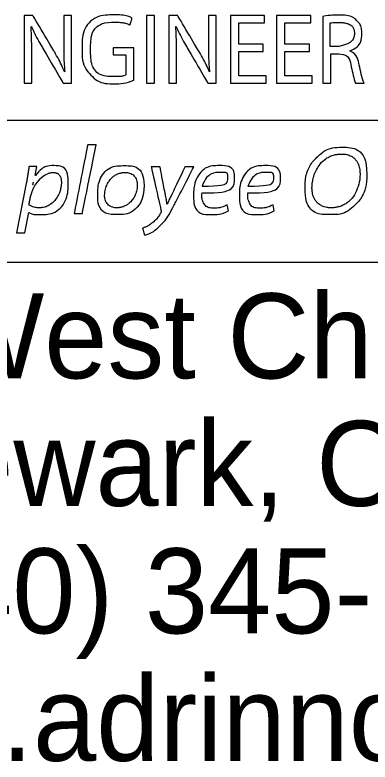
# Model space of a CAD drawing. Extents: x 0 to 34, y 0 to 22.
# Drawn here: x 32.435 to 32.774, y 3.227 to 3.941 of the extents above; entities that cross this region are included whole.
import ezdxf

# ---------------------------------------------------------------- set-up
doc = ezdxf.new("R2010")
doc.units = 0
doc.layers.add('SH_Data', color=7, linetype='Continuous')

msp = doc.modelspace()

# ---------------------------------------------------------------- linework, layer by layer
at = {"layer": 'SH_Data'}
for p, q in [((32.7567, 3.9307), (32.75677, 3.93063)), ((32.73689, 3.91095), (32.73609, 3.91095)), ((32.74792, 3.91193), (32.74453, 3.91095)), ((32.75255, 3.9136), (32.74792, 3.91193)), ((32.75492, 3.90673), (32.75492, 3.90702)), ((32.76039, 3.876), (32.76847, 3.876)), ((32.05557, 3.8407), (33.44039, 3.8407)), ((32.72917, 3.80154), (32.72917, 3.80154)), ((32.63877, 3.75393), (32.63761, 3.75966)), ((32.68262, 3.75393), (32.68145, 3.75966)), ((32.04831, 3.70477), (33.43313, 3.70477))]:
    msp.add_line(p, q, dxfattribs=at)
for points in [[(32.72909, 3.93966), (32.72909, 3.876), (32.73689, 3.876), (32.73689, 3.90395), (32.74425, 3.90395)], [(32.74453, 3.91095), (32.74439, 3.91095), (32.74425, 3.91095)], [(32.45431, 3.78768), (32.45412, 3.78768), (32.45547, 3.79619), (32.44811, 3.79619)], [(32.4455, 3.7802), (32.43611, 3.73303), (32.44405, 3.73303), (32.44782, 3.75236), (32.44802, 3.75236)], [(32.45188, 3.77893), (32.45189, 3.77898), (32.4519, 3.77904)], [(32.45116, 3.75804), (32.44806, 3.75976), (32.44806, 3.75976)], [(32.44806, 3.75976), (32.44806, 3.75976)]]:
    msp.add_lwpolyline(points, dxfattribs=at)
msp.add_arc((32.4781, 3.76327), 0.02878, 114.69426, 168.74282, dxfattribs=at)
for points, degree in [([(32.44333, 3.876), (32.44333, 3.876), (32.44333, 3.94052), (32.44333, 3.94052), (32.44333, 3.94052), (32.45185, 3.94052), (32.45185, 3.94052), (32.45185, 3.94052), (32.47123, 3.90788), (32.47123, 3.90788), (32.47572, 3.90031), (32.47922, 3.89352), (32.48209, 3.88691), (32.48209, 3.88691), (32.48227, 3.88701), (32.48227, 3.88701), (32.48155, 3.89562), (32.48137, 3.90347), (32.48137, 3.91352), (32.48137, 3.91352), (32.48137, 3.94052), (32.48137, 3.94052), (32.48137, 3.94052), (32.48873, 3.94052), (32.48873, 3.94052), (32.48873, 3.94052), (32.48873, 3.876), (32.48873, 3.876), (32.48873, 3.876), (32.48083, 3.876), (32.48083, 3.876), (32.48083, 3.876), (32.46163, 3.90874), (32.46163, 3.90874), (32.45742, 3.91592), (32.45338, 3.92329), (32.45033, 3.93027), (32.45033, 3.93027), (32.45006, 3.93018), (32.45006, 3.93018), (32.45051, 3.92204), (32.45069, 3.91429), (32.45069, 3.90357), (32.45069, 3.90357), (32.45069, 3.876), (32.45069, 3.876), (32.45069, 3.876), (32.44333, 3.876), (32.44333, 3.876)], 3), ([(32.54839, 3.87887), (32.54489, 3.87753), (32.53798, 3.87533), (32.52982, 3.87533), (32.52067, 3.87533), (32.51313, 3.87782), (32.50721, 3.88385), (32.50201, 3.88921), (32.49878, 3.89783), (32.49878, 3.90788), (32.49887, 3.92712), (32.51125, 3.94119), (32.53152, 3.94119), (32.53852, 3.94119), (32.54399, 3.93956), (32.5466, 3.93822), (32.5466, 3.93822), (32.54471, 3.93142), (32.54471, 3.93142), (32.54148, 3.93295), (32.53745, 3.9342), (32.53134, 3.9342), (32.51663, 3.9342), (32.50703, 3.92444), (32.50703, 3.90826), (32.50703, 3.89189), (32.51627, 3.88222), (32.53036, 3.88222), (32.53547, 3.88222), (32.53897, 3.88299), (32.54077, 3.88395), (32.54077, 3.88395), (32.54077, 3.90319), (32.54077, 3.90319), (32.54077, 3.90319), (32.52847, 3.90319), (32.52847, 3.90319), (32.52847, 3.90319), (32.52847, 3.90989), (32.52847, 3.90989), (32.52847, 3.90989), (32.54839, 3.90989), (32.54839, 3.90989), (32.54839, 3.90989), (32.54839, 3.87887), (32.54839, 3.87887)], 3), ([(32.56813, 3.94052), (32.56813, 3.94052), (32.56813, 3.876), (32.56813, 3.876), (32.56813, 3.876), (32.56032, 3.876), (32.56032, 3.876), (32.56032, 3.876), (32.56032, 3.94052), (32.56032, 3.94052), (32.56032, 3.94052), (32.56813, 3.94052), (32.56813, 3.94052)], 3), ([(32.58177, 3.876), (32.58177, 3.876), (32.58177, 3.94052), (32.58177, 3.94052), (32.58177, 3.94052), (32.59029, 3.94052), (32.59029, 3.94052), (32.59029, 3.94052), (32.60967, 3.90788), (32.60967, 3.90788), (32.61416, 3.90031), (32.61766, 3.89352), (32.62053, 3.88691), (32.62053, 3.88691), (32.62071, 3.88701), (32.62071, 3.88701), (32.61999, 3.89562), (32.61981, 3.90347), (32.61981, 3.91352), (32.61981, 3.91352), (32.61981, 3.94052), (32.61981, 3.94052), (32.61981, 3.94052), (32.62717, 3.94052), (32.62717, 3.94052), (32.62717, 3.94052), (32.62717, 3.876), (32.62717, 3.876), (32.62717, 3.876), (32.61927, 3.876), (32.61927, 3.876), (32.61927, 3.876), (32.60007, 3.90874), (32.60007, 3.90874), (32.59585, 3.91592), (32.59182, 3.92329), (32.58876, 3.93027), (32.58876, 3.93027), (32.5885, 3.93018), (32.5885, 3.93018), (32.58894, 3.92204), (32.58912, 3.91429), (32.58912, 3.90357), (32.58912, 3.90357), (32.58912, 3.876), (32.58912, 3.876), (32.58912, 3.876), (32.58177, 3.876), (32.58177, 3.876)], 3), ([(32.67211, 3.90625), (32.67211, 3.90625), (32.64861, 3.90625), (32.64861, 3.90625), (32.64861, 3.90625), (32.64861, 3.88299), (32.64861, 3.88299), (32.64861, 3.88299), (32.67481, 3.88299), (32.67481, 3.88299), (32.67481, 3.88299), (32.67481, 3.876), (32.67481, 3.876), (32.67481, 3.876), (32.6408, 3.876), (32.6408, 3.876), (32.6408, 3.876), (32.6408, 3.94052), (32.6408, 3.94052), (32.6408, 3.94052), (32.67346, 3.94052), (32.67346, 3.94052), (32.67346, 3.94052), (32.67346, 3.93353), (32.67346, 3.93353), (32.67346, 3.93353), (32.64861, 3.93353), (32.64861, 3.93353), (32.64861, 3.93353), (32.64861, 3.91314), (32.64861, 3.91314), (32.64861, 3.91314), (32.67211, 3.91314), (32.67211, 3.91314), (32.67211, 3.91314), (32.67211, 3.90625), (32.67211, 3.90625)], 3), ([(32.71626, 3.90625), (32.71626, 3.90625), (32.69275, 3.90625), (32.69275, 3.90625), (32.69275, 3.90625), (32.69275, 3.88299), (32.69275, 3.88299), (32.69275, 3.88299), (32.71895, 3.88299), (32.71895, 3.88299), (32.71895, 3.88299), (32.71895, 3.876), (32.71895, 3.876), (32.71895, 3.876), (32.68494, 3.876), (32.68494, 3.876), (32.68494, 3.876), (32.68494, 3.94052), (32.68494, 3.94052), (32.68494, 3.94052), (32.7176, 3.94052), (32.7176, 3.94052), (32.7176, 3.94052), (32.7176, 3.93353), (32.7176, 3.93353), (32.7176, 3.93353), (32.69275, 3.93353), (32.69275, 3.93353), (32.69275, 3.93353), (32.69275, 3.91314), (32.69275, 3.91314), (32.69275, 3.91314), (32.71626, 3.91314), (32.71626, 3.91314), (32.71626, 3.91314), (32.71626, 3.90625), (32.71626, 3.90625)], 3), ([(32.75492, 3.90702), (32.76129, 3.90931), (32.76632, 3.91496), (32.76632, 3.92348), (32.76632, 3.92846), (32.76461, 3.93286), (32.76156, 3.93573), (32.7578, 3.93937), (32.75241, 3.94099), (32.74407, 3.94099), (32.73869, 3.94099), (32.73303, 3.94052), (32.72909, 3.93966)], 3), ([(32.73609, 3.93362), (32.73819, 3.93382), (32.74049, 3.93395), (32.74305, 3.93399), (32.74347, 3.93399), (32.74389, 3.93399), (32.74418, 3.93399), (32.74436, 3.93399), (32.74517, 3.93399), (32.74579, 3.93397), (32.74756, 3.93389), (32.74862, 3.93379), (32.75147, 3.93338), (32.75291, 3.93296), (32.75514, 3.93198), (32.75595, 3.93142), (32.7567, 3.9307)], 3), ([(32.73609, 3.91095), (32.73609, 3.91973), (32.73609, 3.92819), (32.73609, 3.93362)], 2), ([(32.75677, 3.93063), (32.75723, 3.9302), (32.75765, 3.92966), (32.7584, 3.92832), (32.75872, 3.92753), (32.75918, 3.9257), (32.75931, 3.92467), (32.75932, 3.92328), (32.75931, 3.92299), (32.75928, 3.92244), (32.75926, 3.92218), (32.75917, 3.92141), (32.75908, 3.92093), (32.75853, 3.91869), (32.75773, 3.91734), (32.75557, 3.91508), (32.75417, 3.91418), (32.75255, 3.9136)], 3), ([(32.74425, 3.91095), (32.74421, 3.91095), (32.73693, 3.91095), (32.73689, 3.91095)], 2), ([(32.76847, 3.876), (32.76721, 3.87849), (32.76578, 3.88471), (32.76381, 3.89371), (32.76237, 3.90041), (32.75959, 3.905), (32.75492, 3.90673)], 3), ([(32.74425, 3.90395), (32.75133, 3.90366), (32.75457, 3.90031), (32.75636, 3.89141), (32.75806, 3.88337), (32.75941, 3.87792), (32.76039, 3.876)], 3), ([(32.49118, 3.75134), (32.49118, 3.75134), (32.50425, 3.817), (32.50425, 3.817), (32.50425, 3.817), (32.51228, 3.817), (32.51228, 3.817), (32.51228, 3.817), (32.49912, 3.75134), (32.49912, 3.75134), (32.49912, 3.75134), (32.49118, 3.75134), (32.49118, 3.75134)], 3), ([(32.77117, 3.78917), (32.77117, 3.80248), (32.7641, 3.81469), (32.74659, 3.81469), (32.73836, 3.81469), (32.73023, 3.81145), (32.72472, 3.80627), (32.71678, 3.79878), (32.71223, 3.78667), (32.71223, 3.77566), (32.71223, 3.76244), (32.72017, 3.75032), (32.73701, 3.75032), (32.74601, 3.75032), (32.75356, 3.75356), (32.75936, 3.75902), (32.7671, 3.76641), (32.77117, 3.77834), (32.77117, 3.78917)], 3), ([(32.72917, 3.80154), (32.73125, 3.8035), (32.73397, 3.80519), (32.7385, 3.80695), (32.74008, 3.80741), (32.74251, 3.80788), (32.74332, 3.80799), (32.74455, 3.80811), (32.74516, 3.80816), (32.74587, 3.80818), (32.74623, 3.80819), (32.74641, 3.80819), (32.7465, 3.80819), (32.74654, 3.80819), (32.74656, 3.80819), (32.74656, 3.80819), (32.75021, 3.80819), (32.75302, 3.80757), (32.75745, 3.80565), (32.75911, 3.80436), (32.76182, 3.80113), (32.76287, 3.79915), (32.7643, 3.79454), (32.76467, 3.79192), (32.76467, 3.78917)], 3), ([(32.75489, 3.76373), (32.75313, 3.76208), (32.75121, 3.76071), (32.74701, 3.75855), (32.74474, 3.75776), (32.74102, 3.75706), (32.73972, 3.75691), (32.73803, 3.75684), (32.7376, 3.75682), (32.73714, 3.75682), (32.73704, 3.75682), (32.73699, 3.75682), (32.73694, 3.75682), (32.73682, 3.75682), (32.73642, 3.75682), (32.73603, 3.75684), (32.7345, 3.75691), (32.73338, 3.75705), (32.73025, 3.75766), (32.72851, 3.75833), (32.72552, 3.76004), (32.72427, 3.76109), (32.72212, 3.76354), (32.72123, 3.76496), (32.71983, 3.76815), (32.71932, 3.76991), (32.71888, 3.77272), (32.71879, 3.77369), (32.71874, 3.77492), (32.71873, 3.77517), (32.71873, 3.77554), (32.71873, 3.77566), (32.71873, 3.77588), (32.71873, 3.77642), (32.71875, 3.77697), (32.71886, 3.77917), (32.71909, 3.78097), (32.72015, 3.78638), (32.72139, 3.78998), (32.72471, 3.79644), (32.72681, 3.79931), (32.72917, 3.80154)], 3), ([(32.44811, 3.79619), (32.44744, 3.79166), (32.44647, 3.78556), (32.4455, 3.7802)], 2), ([(32.44802, 3.75236), (32.44986, 3.75134), (32.45315, 3.75032), (32.45818, 3.75032), (32.47376, 3.75032), (32.48557, 3.76521), (32.48557, 3.78093), (32.48557, 3.78917), (32.48131, 3.79712), (32.47115, 3.79712), (32.46476, 3.79712), (32.45857, 3.79351), (32.45431, 3.78768)], 3), ([(32.55816, 3.77844), (32.55816, 3.78796), (32.55254, 3.79712), (32.53986, 3.79712), (32.52467, 3.79712), (32.51393, 3.78343), (32.51393, 3.76873), (32.51393, 3.75865), (32.52051, 3.75032), (32.53222, 3.75032), (32.5479, 3.75032), (32.55816, 3.76466), (32.55816, 3.77844)], 3), ([(32.57335, 3.7961), (32.57335, 3.7961), (32.57799, 3.77206), (32.57799, 3.77206), (32.57906, 3.76688), (32.57964, 3.76355), (32.58013, 3.76022), (32.58013, 3.76022), (32.58032, 3.76022), (32.58032, 3.76022), (32.58158, 3.76308), (32.58293, 3.76623), (32.58535, 3.77113), (32.58535, 3.77113), (32.59725, 3.7961), (32.59725, 3.7961), (32.59725, 3.7961), (32.60577, 3.7961), (32.60577, 3.7961), (32.60577, 3.7961), (32.58825, 3.76207), (32.58825, 3.76207), (32.58322, 3.75236), (32.57848, 3.7445), (32.57209, 3.73858), (32.56686, 3.73349), (32.56115, 3.73136), (32.55845, 3.73081), (32.55845, 3.73081), (32.55651, 3.73737), (32.55651, 3.73737), (32.55854, 3.73811), (32.56193, 3.73932), (32.56512, 3.74172), (32.56822, 3.74403), (32.57161, 3.74764), (32.57412, 3.75199), (32.57451, 3.75273), (32.57451, 3.75328), (32.57442, 3.75402), (32.57442, 3.75402), (32.56503, 3.7961), (32.56503, 3.7961), (32.56503, 3.7961), (32.57335, 3.7961), (32.57335, 3.7961)], 3), ([(32.61361, 3.77104), (32.63093, 3.77076), (32.64477, 3.7739), (32.64477, 3.78565), (32.64477, 3.79203), (32.63993, 3.79712), (32.63103, 3.79712), (32.61593, 3.79712), (32.60548, 3.78186), (32.60548, 3.76836), (32.60548, 3.75846), (32.6109, 3.75032), (32.62329, 3.75032), (32.62957, 3.75032), (32.63529, 3.75199), (32.63877, 3.75393)], 3), ([(32.65745, 3.77104), (32.67477, 3.77076), (32.68861, 3.7739), (32.68861, 3.78565), (32.68861, 3.79203), (32.68378, 3.79712), (32.67487, 3.79712), (32.65977, 3.79712), (32.64932, 3.78186), (32.64932, 3.76836), (32.64932, 3.75846), (32.65474, 3.75032), (32.66713, 3.75032), (32.67342, 3.75032), (32.67913, 3.75199), (32.68262, 3.75393)], 3), ([(32.46608, 3.78942), (32.4664, 3.78957), (32.46671, 3.78971), (32.46835, 3.79033), (32.46967, 3.79059), (32.47105, 3.79062), (32.47112, 3.79062), (32.47133, 3.79062), (32.47164, 3.79061), (32.47193, 3.7906), (32.47248, 3.79055), (32.47282, 3.7905), (32.47377, 3.79032), (32.47429, 3.79015), (32.47565, 3.78954), (32.47632, 3.78901), (32.47753, 3.78752), (32.47806, 3.78654), (32.47882, 3.78413), (32.47904, 3.78272), (32.47907, 3.78105), (32.47907, 3.78086), (32.47907, 3.78044), (32.47905, 3.7798), (32.47896, 3.77833), (32.47879, 3.77707), (32.47801, 3.77292), (32.47675, 3.76972), (32.47323, 3.76416), (32.47099, 3.76181), (32.46597, 3.75837), (32.46321, 3.75729), (32.45985, 3.7569), (32.45928, 3.75685), (32.45861, 3.75682), (32.45833, 3.75682), (32.4582, 3.75682), (32.45818, 3.75682), (32.4581, 3.75682), (32.45797, 3.75682), (32.45654, 3.75684), (32.45537, 3.75694), (32.45263, 3.75737), (32.45153, 3.75784), (32.45116, 3.75804)], 3), ([(32.52043, 3.76873), (32.52043, 3.77161), (32.52096, 3.77447), (32.52291, 3.77974), (32.52434, 3.78215), (32.52785, 3.78618), (32.52992, 3.78779), (32.53337, 3.78945), (32.53458, 3.78987), (32.53648, 3.79031), (32.53713, 3.79043), (32.53814, 3.79054), (32.53865, 3.79058), (32.53925, 3.79061), (32.53951, 3.79062), (32.53969, 3.79062), (32.53979, 3.79062), (32.54225, 3.79062), (32.54406, 3.7902), (32.54689, 3.78896), (32.54795, 3.78815), (32.54972, 3.78608), (32.55042, 3.78482), (32.55139, 3.78186), (32.55166, 3.78018), (32.55166, 3.77844)], 3), ([(32.61363, 3.77758), (32.61643, 3.78502), (32.62261, 3.79062), (32.63103, 3.79062), (32.63715, 3.79062), (32.63827, 3.78943), (32.63827, 3.78565), (32.63827, 3.77966), (32.63157, 3.77762), (32.61363, 3.77758)], 3), ([(32.65748, 3.77758), (32.66027, 3.78502), (32.66645, 3.79062), (32.67487, 3.79062), (32.68099, 3.79062), (32.68211, 3.78943), (32.68211, 3.78565), (32.68211, 3.77966), (32.67541, 3.77762), (32.65748, 3.77758)], 3), ([(32.76467, 3.78917), (32.76467, 3.78457), (32.76379, 3.77961), (32.7604, 3.77062), (32.7579, 3.76662), (32.75489, 3.76373)], 3), ([(32.4519, 3.77904), (32.45202, 3.77975), (32.45215, 3.78046), (32.45228, 3.78118)], 2), ([(32.55166, 3.77844), (32.55166, 3.7758), (32.55116, 3.77306), (32.54926, 3.76789), (32.54786, 3.76547), (32.54438, 3.76139), (32.54232, 3.75974), (32.53886, 3.75804), (32.53764, 3.7576), (32.5357, 3.75714), (32.53503, 3.75702), (32.534, 3.7569), (32.53348, 3.75686), (32.53285, 3.75683), (32.53254, 3.75682), (32.5324, 3.75682), (32.53231, 3.75682), (32.53225, 3.75682), (32.53006, 3.75682), (32.52833, 3.7572), (32.52549, 3.75837), (32.52437, 3.75917), (32.52251, 3.76117), (32.52177, 3.76239), (32.52072, 3.76526), (32.52043, 3.76691), (32.52043, 3.76873)], 3), ([(32.63761, 3.75966), (32.6347, 3.75818), (32.63054, 3.75652), (32.62503, 3.75652), (32.62019, 3.75652), (32.61642, 3.75855), (32.61458, 3.76253), (32.61351, 3.76493), (32.61322, 3.7691), (32.61361, 3.77104)], 3), ([(32.68145, 3.75966), (32.67855, 3.75818), (32.67439, 3.75652), (32.66887, 3.75652), (32.66403, 3.75652), (32.66026, 3.75855), (32.65842, 3.76253), (32.65735, 3.76493), (32.65706, 3.7691), (32.65745, 3.77104)], 3), ([(32.44806, 3.75976), (32.44871, 3.76301), (32.44933, 3.76614), (32.44988, 3.76889)], 2), ([(32.44802, 3.75886), (32.44802, 3.75886), (32.44794, 3.75886), (32.44788, 3.75886)], 2)]:
    msp.add_open_spline(points, degree=degree, dxfattribs=at)

# ---------------------------------------------------------------- texts
for s, p in [('88 West Church Street', (32.20907, 3.59376)), ('Newark, OH 43055', (32.29431, 3.47189)), ('(740) 345-1921 (ph)', (32.27515, 3.35001)), ('www.adrinnovation.com', (32.18636, 3.22814))]:
    msp.add_text(s, height=0.0812498, rotation=360, dxfattribs=at).set_placement(p)

doc.saveas('drawing.dxf')
